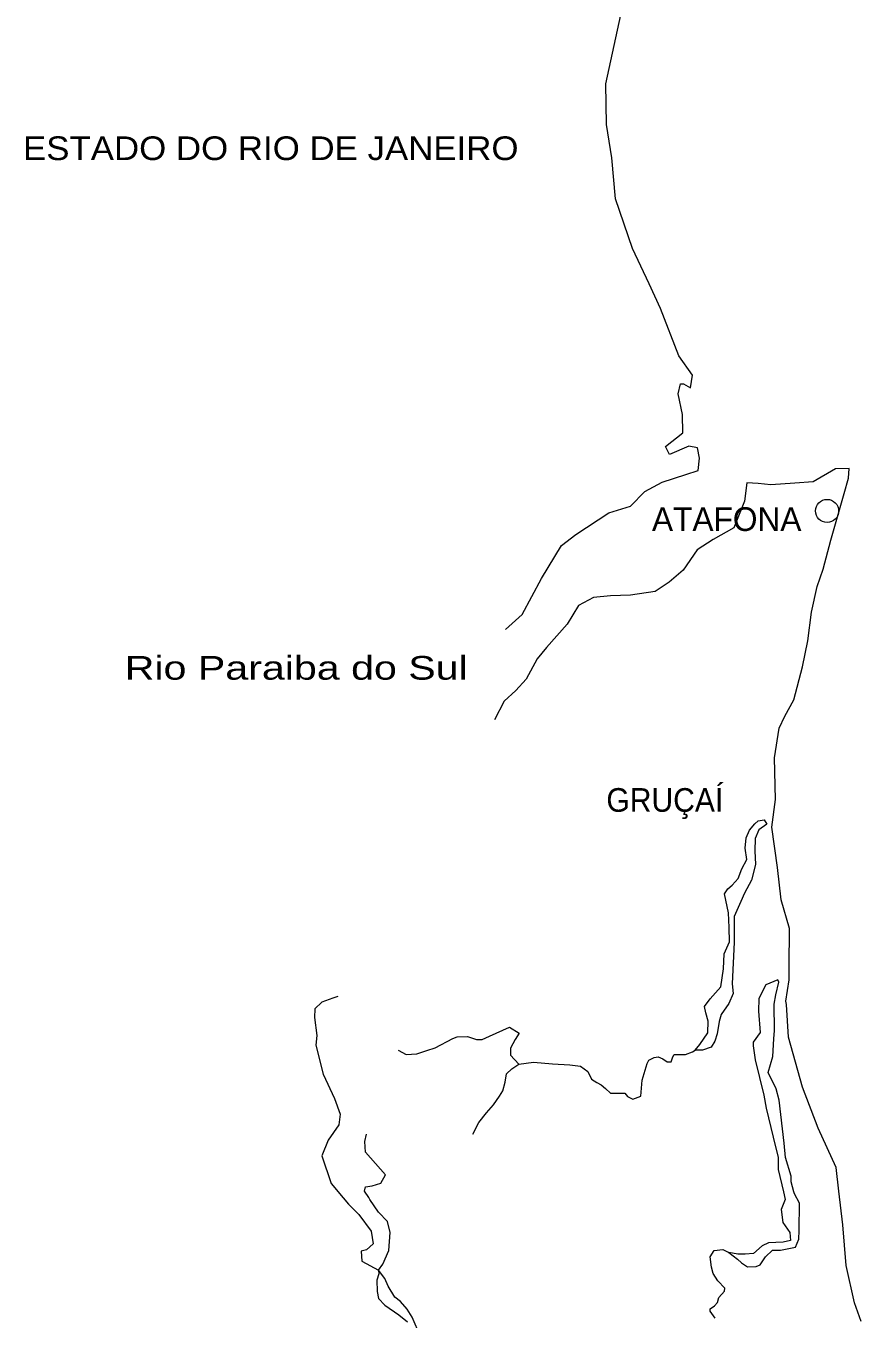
# Model space of a CAD drawing. Extents: x 47169 to 972804, y 7447977 to 9608469.
# Drawn here: x 269976 to 292406, y 7585503 to 7620223 of the extents above; entities that cross this region are included whole.
import ezdxf

# ---------------------------------------------------------------- set-up
doc = ezdxf.new("R2010")
doc.units = 0
doc.header["$LTSCALE"] = 270
doc.layers.add('1', color=7, linetype='Continuous', lineweight=13)
doc.layers.add('2', color=7, linetype='Continuous', lineweight=13)
doc.layers.add('3', color=7, linetype='Continuous')

msp = doc.modelspace()

# ---------------------------------------------------------------- linework, layer by layer
at = {"layer": '1'}
for points in [[(282856.9, 7604017.9), (283307, 7604422.7), (283822.2, 7605382.2), (284359, 7606275.4), (284748.6, 7606568.6), (285631.5, 7607145.3), (286209, 7607330.2), (286597.3, 7607723), (287060.1, 7607972.8), (287699.5, 7608180.6), (288029.5, 7608284.6), (288066.5, 7608617.3), (288011.1, 7608893.5), (287782.7, 7608934.8), (287257.4, 7608717.4), (287151, 7608926.5), (287622.6, 7609298.2), (287605.8, 7609785.3), (287494.8, 7610348.6), (287553.4, 7610615.2), (287636.2, 7610616.3), (287824.1, 7610508), (287881.9, 7610841.1), (287512.4, 7611367.8), (287019.2, 7612635), (286710, 7613295.4), (286262.3, 7614242), (285809.5, 7615576.1), (285711.9, 7616682.4), (285565.3, 7617577.5), (285550.9, 7618662.7), (286000.3, 7620728.7)], [(290356.7, 7601692.1), (290598.4, 7602129.4), (290832.2, 7603016.2), (290978.4, 7603715.9), (291072, 7604481.3), (291228.7, 7605170), (291388.3, 7605637.2), (291595.7, 7606415.2), (291803.4, 7607171), (291952.2, 7607671.3), (292071.2, 7608082.6), (292088.6, 7608337.5), (291715.8, 7608332.7), (291119.7, 7607981.7), (290623.1, 7607942), (289981.6, 7607900.4), (289639.3, 7607940.2), (289338.7, 7607958.4), (289272.8, 7607459.2), (288992.1, 7606746.7), (288437.1, 7606429.3), (288005.7, 7606157.8), (287629.8, 7605610.1), (287251, 7605284), (286871.2, 7605035.2), (286209.8, 7604937.9), (285671.6, 7604919.6), (285216.5, 7604880.3), (284815.5, 7604664.5), (284511.6, 7604162), (283960.9, 7603534.4), (283706.2, 7603231.9), (283413.3, 7602685.3), (283129.5, 7602381.3), (282823.9, 7602089.2), (282561.5, 7601588.3)], [(291808.7, 7588936.2), (291732, 7589571.4), (291252.6, 7590628.4), (290834.7, 7591730.5), (290455, 7593076.7), (290402.1, 7593951), (290380.3, 7594039.3), (290476.2, 7594616.5), (290471.7, 7594959.7), (290478.9, 7595989.9), (290261.8, 7596762.3), (290157.4, 7597624.8), (290008.6, 7598708.2), (290102.4, 7599451.5), (290077.4, 7600569.8), (290201.5, 7601368.8), (290356.7, 7601692.1)], [(290600, 7588920.4), (290526.7, 7589190.2), (290524.6, 7589345.2), (290373.3, 7589841.6), (290337.2, 7590228.8), (290208.3, 7591378.9), (290121.4, 7591687.9), (289908.7, 7592128.1), (290037.7, 7592550.7), (290062.5, 7593027.3), (290080.2, 7593249), (290070.9, 7593957.7), (290119.3, 7594213.1), (290197.7, 7594546.4), (290165.8, 7594612.4), (289846.8, 7594475.3), (289655.1, 7594107.3), (289649.1, 7593775), (289698, 7593199.7), (289504.8, 7592942.4), (289506.2, 7592842.7), (289562.8, 7592466.9), (289792.6, 7591517.4), (289859.3, 7591163.9), (290045.4, 7590391.1), (290176.8, 7589839), (290181, 7589517.9), (290320, 7588916.8)], [(278354.3, 7594165.1), (278220.5, 7594118.9), (277921.8, 7594015.1), (277738, 7593835.3), (277730.9, 7593602.6), (277789.4, 7593116.1), (277761.9, 7592860.9), (277959.1, 7592077.3), (278268.1, 7591428), (278418.8, 7591009.2), (278381.4, 7590720.7), (278097.5, 7590307), (277927.5, 7589883.7), (278175.7, 7589145), (278497.4, 7588757)], [(279978.1, 7592725.5), (280186.7, 7592606.5), (280476.2, 7592621.5), (280744, 7592713.8), (280970.7, 7592783.4), (281443.2, 7593033.5), (281556.4, 7593079.4), (281835.6, 7593094.3), (282074.8, 7593008.9), (282230, 7593011), (282425.3, 7593102.3), (282785.3, 7593262.3), (282960.1, 7593342.2), (283221, 7593179.6), (283119.8, 7593012.1), (282988.5, 7592777.7), (282991, 7592589.4), (283211.6, 7592348.8)], [(281974.9, 7590471.2), (282136.2, 7590783.5), (282349.9, 7591041.2), (282533.2, 7591254.1), (282695.6, 7591488.9), (282786.7, 7591634.1), (282845.6, 7591867.5), (282884, 7592089.6), (283027, 7592224.4), (283211.6, 7592348.8), (283604.1, 7592398.4), (284121.9, 7592361.1), (284587.9, 7592334.2), (284867.8, 7592293.6), (285066.3, 7592152.3), (285162.2, 7591943.2), (285308.2, 7591856.5), (285422.9, 7591791.6), (285538, 7591693.5), (285674.2, 7591573.5), (286057, 7591567.5), (286130.6, 7591479.9), (286276.5, 7591404.3), (286492.7, 7591484.7), (286528.3, 7591917.2), (286656.9, 7592361.9), (286707.4, 7592451.2), (286851.2, 7592530.6), (286954.5, 7592543.1), (287079.4, 7592489.4), (287194.2, 7592413.4), (287308, 7592414.9), (287347.6, 7592548.3), (287388.2, 7592604.2), (287615.8, 7592607.3), (287688.2, 7592608.2), (287873.6, 7592677.2), (287945.4, 7592722.4)], [(279182.5, 7588766.5), (279068.3, 7588935.9), (279097.6, 7589058.2), (279273.1, 7589082.7), (279510.1, 7589152.5), (279631.2, 7589375.7), (279368.3, 7589682.2), (279095.1, 7589988.5), (279080.8, 7590276.3), (279119.5, 7590465.1)], [(278497.4, 7588757), (278638.6, 7588586.6), (278921.7, 7588313.6), (279248.6, 7587864), (279305.1, 7587521.4), (279121.1, 7587363.8), (278976.8, 7587328.6), (279001.1, 7587063.1), (279449.4, 7586814.5)], [(279449.4, 7586814.5), (279560.8, 7586982.2), (279721.2, 7587350), (279756, 7587826.7), (279689.8, 7588124.9), (279448.4, 7588376.3), (279216.2, 7588716.4), (279182.5, 7588766.5)], [(290320, 7588916.8), (290367.5, 7588711.8), (290257.2, 7588444.6), (290303.1, 7588101.8), (290492.9, 7587827.4), (290506, 7587617.2), (290310, 7587570.3), (289917.2, 7587554.1), (289752.8, 7587474.4), (289517.7, 7587260.8), (289290.3, 7587246.7), (289093.9, 7587244.1), (288855.3, 7587296.4)], [(290740.3, 7587886.1), (290751.4, 7588617.2), (290613.6, 7588870.1), (290600, 7588920.4)], [(292406.5, 7585438), (292224, 7585945.1), (292004.2, 7586939), (291917.5, 7588034.4), (291808.7, 7588936.2)], [(288855.3, 7587296.4), (289085.3, 7587111.1), (289190, 7587012.8), (289356.9, 7586904.3), (289584.3, 7586918.4), (289697.5, 7586964.2), (289839.5, 7587176.5), (290023.3, 7587356.1), (290240.4, 7587359), (290642.9, 7587430.7), (290733, 7587653.4), (290740.3, 7587886.1)], [(288485.7, 7585530.4), (288348.8, 7585716.9), (288347.9, 7585783.3), (288470.9, 7585862.5), (288552.5, 7585952.2), (288581.7, 7586085.5), (288734.6, 7586253.7), (288744, 7586331.3), (288555.2, 7586528.2), (288428.4, 7586725.8), (288384.7, 7586902.5), (288350, 7587178.9), (288461.6, 7587346.5), (288688.8, 7587371.7), (288855.3, 7587296.4)], [(280570.3, 7585035.7), (280346, 7585553.2), (280218.8, 7585772.9), (280040.1, 7585980.9), (279883.5, 7586089.5), (279703.5, 7586386.1), (279617.9, 7586595.4), (279449.4, 7586814.5), (279450.7, 7586714.9), (279401.3, 7586548), (279405.5, 7586249), (279449.4, 7586061.4), (279617.5, 7585875.4), (279993.4, 7585614.8), (280223.5, 7585429.6)]]:
    msp.add_lwpolyline(points, dxfattribs=at)
msp.add_lwpolyline([(287945.4, 7592722.4), (288077.8, 7592879.2), (288291, 7593192.2), (288297.2, 7593502.4), (288232.2, 7593723), (288198.8, 7593899.8), (288351.4, 7594101.2), (288636.8, 7594426.1), (288713.3, 7594903.4), (288728.5, 7595313.4), (288869.2, 7595636.4), (288864.2, 7596012.9), (288848.6, 7596411.5), (288738.4, 7596919.5), (288829.8, 7597053.6), (288942.3, 7597154.7), (289105.5, 7597334.1), (289205.6, 7597590.2), (289336.8, 7597846.6), (289291.5, 7598145), (289318.9, 7598422.3), (289409.2, 7598633.9), (289552, 7598801.9), (289644.1, 7598880.7), (289799, 7598904.8), (289872.9, 7598795.1), (289657.6, 7598637.2), (289557.2, 7598403.3), (289551.2, 7598070.9), (289566.4, 7597705.7), (289458.1, 7597283.4), (289276.3, 7596937.6), (289175.8, 7596714.8), (288994.8, 7596313.7), (288993.5, 7595627), (288946.1, 7594507.8), (288970.3, 7594242.3), (288849.7, 7593974.8), (288646.6, 7593684.2), (288597.4, 7593495.3), (288539.7, 7593162.2), (288480.2, 7592962.1), (288378.9, 7592805.7), (288141.9, 7592725)], close=True, dxfattribs=at)
at = {"layer": '2'}
msp.add_circle((291492.3, 7607200.2), 310.5, dxfattribs=at)

# ---------------------------------------------------------------- texts
at = {"layer": '3'}
for s, height, width, p in [('ESTADO DO RIO DE JANEIRO', 636, 1.1, (269899, 7616619.9)), ('Rio Paraiba do Sul', 635.5, 1.3, (272630.2, 7602670.5)), ('GRUÇAÍ', 635.3, 0.95, (285565.5, 7599123.3))]:
    msp.add_text(s, height=height, dxfattribs=dict(at, width=width)).set_placement(p)
msp.add_text('ATAFONA', height=635.6, dxfattribs=at).set_placement((286789.3, 7606663.1))

doc.saveas('drawing.dxf')
